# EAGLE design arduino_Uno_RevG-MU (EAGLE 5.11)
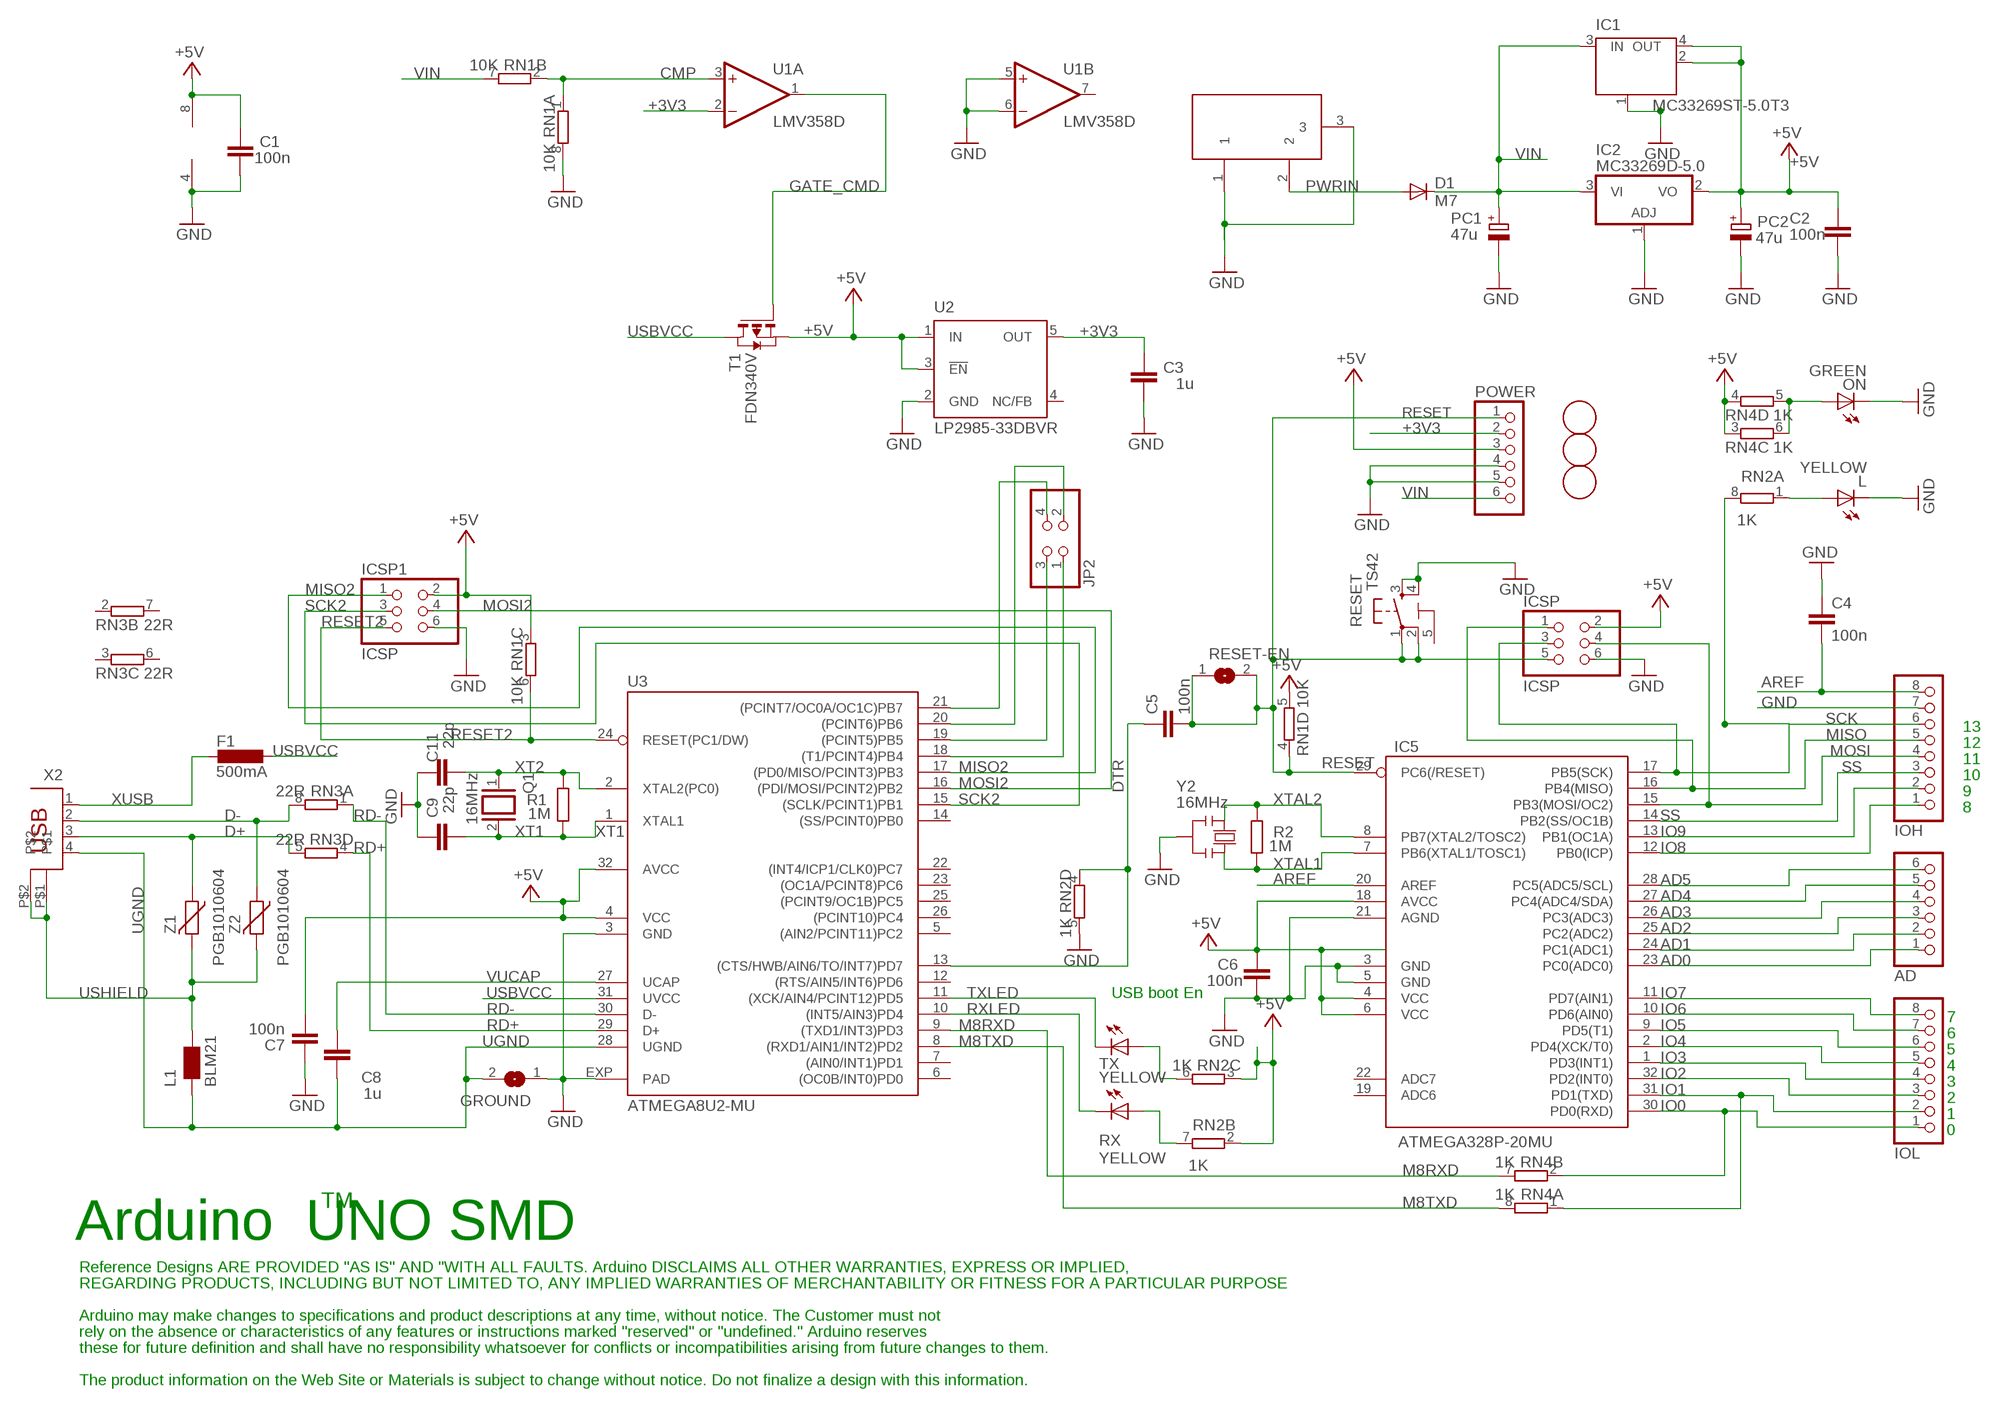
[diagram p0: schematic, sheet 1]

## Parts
AD  PINHD-1X6  [1X06]
C1  100n  C-EU0603-RND  [C0603-ROUND]
C2  100n  C-EU0603-RND  [C0603-ROUND]
C3  1u  C-EU0603-RND  [C0603-ROUND]
C4  100n  C-EU0603-RND  [C0603-ROUND]
C5  100n  C-EU0603-RND  [C0603-ROUND]
C6  100n  C-EU0603-RND  [C0603-ROUND]
C7  100n  C-EU0603-RND  [C0603-ROUND]
C8  1u  C-EU0603-RND  [C0603-ROUND]
C9  22p  C-EU0603-RND  [C0603-ROUND]
C11  22p  C-EU0603-RND  [C0603-ROUND]
D1  M7  DIODE-SMB  [SMB]
F1  500mA  L-EUL1812  [L1812]
GROUND  SJ  [SJ]
IC1  MC33269ST-5.0T3  MC33269ST-3.3T3  [SOT223]
IC2  MC33269D-5.0  [DPACK]
IC5  ATMEGA328P-20MU  MEGA8-MI  [MLF32]
ICSP  ICSP  PINHD-2X3  [2X03]
ICSP1  ICSP  PINHD-2X3  [2X03]
IOH  PINHD-1X8  [1X08]
IOL  PINHD-1X8  [1X08]
JP2  PINHD-2X2  [2X02]
L  YELLOW  LEDCHIP-LED0805  [CHIP-LED0805]
L1  BLM21  WE-CBF_0805  [0805]
ON  GREEN  LEDCHIP-LED0805  [CHIP-LED0805]
PC1  47u  CPOL-EUD  [PANASONIC_D]
PC2  47u  CPOL-EUD  [PANASONIC_D]
POWER  PINHD-1X6  [1X06]
Q1  16MHz  XTAL/S  [QS]
R1  1M  R-EU_R0603  [R0603-ROUND]
R2  1M  R-EU_R0603  [R0603-ROUND]
RESET  TS42  [TS42]
RESET-EN  SJ  [SJ]
RN1  10K  4R-NCAY16  [CAY16]
RN2  1K  4R-NCAY16  [CAY16]
RN3  22R  4R-NCAY16  [CAY16]
RN4  1K  4R-NCAY16  [CAY16]
RX  YELLOW  LEDCHIP-LED0805  [CHIP-LED0805]
T1  FDN340V  PMOSSOT23  [SOT-23]
TX  YELLOW  LEDCHIP-LED0805  [CHIP-LED0805]
U1  LMV358D  LM358D  [SO08]
U2  LP2985-33DBVR  TPS77033  [SOT23-DBV]
U3  ATMEGA8U2-MU  [QFN32]
U$3  FIDUCIALMOUNT  [FIDUCIA-MOUNT]
U$4  FIDUCIALMOUNT  [FIDUCIA-MOUNT]
U$6  FIDUCIALMOUNT  [FIDUCIA-MOUNT]
X1  DC21MMX  [DC-21MM]
X2  PN61729  [PN61729]
Y2  16MHz  RESONATORMU  [RESONATOR]
Z1  PGB1010604  VARISTORCN0603  [CT/CN0603]
Z2  PGB1010604  VARISTORCN0603  [CT/CN0603]

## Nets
+3V3: C3.2 POWER.2 U1.2(A:-IN) U2.5(OUT)
+5V [usbvcc]: C1.2 C2.2 C6.2 C7.1 IC1.2(OUT) IC1.4(OUT) IC2.2(VO) IC5.4(VCC) IC5.6(VCC) IC5.18(AVCC) ICSP1.2 ICSP.2 PC2.+ POWER.3 RN1.3 RN1.5 RN2.2 RN2.3 RN4.3 RN4.4 T1.2(S) U1.8(P:V+) U2.1(IN) U2.3(!EN) U3.4(VCC) U3.32(AVCC)
AD0: AD.1 IC5.23(PC0(ADC0))
AD1: AD.2 IC5.24(PC1(ADC1))
AD2: AD.3 IC5.25(PC2(ADC2))
AD3: AD.4 IC5.26(PC3(ADC3))
AD4: AD.5 IC5.27(PC4(ADC4/SDA))
AD5: AD.6 IC5.28(PC5(ADC5/SCL))
AREF [aref]: C4.2 IC5.20(AREF) IOH.8
CMP: RN1.1 RN1.2 U1.3(A:+IN)
D+: RN3.5 X2.3 Z1.1
D-: RN3.8 X2.2 Z2.1
DTR: C5.1 RN2.4 U3.13((CTS/HWB/AIN6/TO/INT7)PD7)
GATE_CMD: T1.3(G) U1.1(A:OUT)
GND [gnd]: C1.1 C2.1 C3.1 C4.1 C6.1 C7.2 C9.2 C11.2 GROUND.1 IC1.1(GND/ADJ) IC2.1(ADJ) IC5.3(GND) IC5.5(GND) IC5.21(AGND) ICSP1.6 ICSP.6 IOH.7 L.C ON.C PC1.- PC2.- POWER.4 POWER.5 RESET.3 RESET.4 RN1.8 RN2.5 U1.4(P:V-) U1.5(B:+IN) U1.6(B:-IN) U2.2(GND) U3.3(GND) U3.EXP(PAD) X1.1 X1.3 Y2.2
IO0: IC5.30(PD0(RXD)) IOL.1 RN4.2
IO1: IC5.31(PD1(TXD)) IOL.2 RN4.1
IO2: IC5.32(PD2(INT0)) IOL.3
IO3: IC5.1(PD3(INT1)) IOL.4
IO4: IC5.2(PD4(XCK/T0)) IOL.5
IO5: IC5.9(PD5(T1)) IOL.6
IO6: IC5.10(PD6(AIN0)) IOL.7
IO7: IC5.11(PD7(AIN1)) IOL.8
IO8: IC5.12(PB0(ICP)) IOH.1
IO9: IC5.13(PB1(OC1A)) IOH.2
M8RXD: RN4.7 U3.9((TXD1/INT3)PD3)
M8TXD: RN4.8 U3.8((RXD1/AIN1/INT2)PD2)
MISO: IC5.16(PB4(MISO)) ICSP.1 IOH.5
MISO2: ICSP1.1 U3.17((PD0/MISO/PCINT3)PB3)
MOSI: IC5.15(PB3(MOSI/OC2)) ICSP.4 IOH.4
MOSI2: ICSP1.4 U3.16((PDI/MOSI/PCINT2)PB2)
N$1: L.A RN2.1
N$2: JP2.1 U3.18((T1/PCINT4)PB4)
N$3: ON.A RN4.5 RN4.6
N$4: JP2.3 U3.19((PCINT5)PB5)
N$5: JP2.2 U3.20((PCINT6)PB6)
N$6: JP2.4 U3.21((PCINT7/OC0A/OC1C)PB7)
N$35: RN2.7 RX.A
N$36: RN2.6 TX.A
PWRIN [power]: D1.A X1.2
RD+: RN3.4 U3.29(D+)
RD-: RN3.1 U3.30(D-)
RESET: C5.2 IC5.29(PC6(/RESET)) ICSP.5 POWER.1 RESET-EN.1 RESET-EN.2 RESET.1 RESET.2 RN1.4
RESET2: ICSP1.5 RN1.6 U3.24(RESET(PC1/DW))
RXLED: RX.C U3.10((INT5/AIN3)PD4)
SCK: IC5.17(PB5(SCK)) ICSP.3 IOH.6 RN2.8
SCK2: ICSP1.3 U3.15((SCLK/PCINT1)PB1)
SS: IC5.14(PB2(SS/OC1B)) IOH.3
TXLED: TX.C U3.11((XCK/AIN4/PCINT12)PD5)
UGND [gnd]: C8.2 GROUND.2 L1.1 U3.28(UGND) X2.4
USBVCC [usbvcc]: F1.1 T1.1(D) U3.31(UVCC)
USHIELD [gnd]: L1.2 X2.P$1 X2.P$2 Z1.2 Z2.2
VIN [power]: D1.C IC1.3(IN) IC2.3(VI) PC1.+ POWER.6 RN1.7
VUCAP: C8.1 U3.27(UCAP)
XT1: C9.1 Q1.2 R1.1 U3.1(XTAL1)
XT2: C11.1 Q1.1 R1.2 U3.2(XTAL2(PC0))
XTAL1: IC5.7(PB6(XTAL1/TOSC1)) R2.1 Y2.3
XTAL2: IC5.8(PB7(XTAL2/TOSC2)) R2.2 Y2.1
XUSB [usbvcc]: F1.2 X2.1
Unconnected: IC5.19(ADC6) IC5.22(ADC7) RN3.2 RN3.3 RN3.6 RN3.7 U1.7(B:OUT) U2.4(NC/FB) U3.5((AIN2/PCINT11)PC2) U3.6((OC0B/INT0)PD0) U3.7((AIN0/INT1)PD1) U3.12((RTS/AIN5/INT6)PD6) U3.14((SS/PCINT0)PB0) U3.22((INT4/ICP1/CLK0)PC7) U3.23((OC1A/PCINT8)PC6) U3.25((PCINT9/OC1B)PC5) U3.26((PCINT10)PC4)

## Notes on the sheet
- 13
- 12
- 11
- 10
- 9
- 8
- USB boot En
- 7
- 6
- 5
- 4
- 3
- 2
- 1
- 0
- TM
- Arduino  UNO SMD
- Reference Designs ARE PROVIDED "AS IS" AND "WITH ALL FAULTS. Arduino DISCLAIMS ALL OTHER WARRANTIES, EXPRESS OR IMPLIED,
- REGARDING PRODUCTS, INCLUDING BUT NOT LIMITED TO, ANY IMPLIED WARRANTIES OF MERCHANTABILITY OR FITNESS FOR A PARTICULAR PURPOSE
- Arduino may make changes to specifications and product descriptions at any time, without notice. The Customer must not
- rely on the absence or characteristics of any features or instructions marked "reserved" or "undefined." Arduino reserves
- these for future definition and shall have no responsibility whatsoever for conflicts or incompatibilities arising from future changes to them.
- The product information on the Web Site or Materials is subject to change without notice. Do not finalize a design with this information.

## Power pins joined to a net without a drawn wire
5-GND: RESET.5(5-GND)

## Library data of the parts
AD POWER = pinhead:PINHD-1X6: PIN HEADER
C1-C9 C11 = SmartPrj:C-EU: CAPACITOR, European symbol
D1 = diode:DIODE-: DIODE
F1 = rcl:L-EU: INDUCTOR, European symbol
GROUND RESET-EN = jumper:SJ: SMD solder JUMPER
IC1 = linear:MC33269ST*: Adjustable Output Low Dropout Voltage Regulator 800 mA Source: http://www.onsemi.com/pub/Collateral/MC33269-D.PDF
IC2 = linear:MC33269?*: Adjustable Output Low Dropout Voltage Regulator 800 mA Source: http://www.onsemi.com/pub/Collateral/MC33269-D.PDF
IC5 = idii:MEGA8: MICROCONTROLLER 8 Kbytes FLASH 1 kbytes SRAM 512 bytes EEPROM USART 6-channel 10 bit ADC 2-channel 8 bit ADC Source: avr.lbr
ICSP ICSP1 = pinhead:PINHD-2X3: PIN HEADER
IOH IOL = pinhead:PINHD-1X8: PIN HEADER
JP2 = pinhead:PINHD-2X2: PIN HEADER
L ON RX TX = led:LED: LED
L1 = wuerth-elektronik:WE-CBF: SMD EMI Suppression Ferrite Beads
PC1 PC2 = rcl:CPOL-EU: POLARIZED CAPACITOR, European symbol
Q1 = special:XTAL/S: CRYSTAL
R1 R2 = SmartPrj:R-EU_: RESISTOR, European symbol
RESET = st-mod v1.4:TS42: TS42 Dongnan Electronics Tact switch VDC 12V - 50mA
RN1-RN4 = resistor-dil:4R-N: Array Chip Resistor Source: RS Component / Phycomp
T1 = zetex:PMOSSOT23: MOS FET
U1 = linear:LM358: OP AMP also LM158; LM258; LM2904 Source: http://cache.national.com/ds/LM/LM158.pdf
U2 = texas:TPS770*: ULTRALOW-POWER 50-mA LOW-DROPOUT LINEAR REGULATORS 50-mA Low-Dropout Regulator Source: http://focus.ti.com/lit/ds/symlink/tps77001.pdf
U3 = atmel:ATMEGA8U2-MU
U$3 U$4 U$6 = SmartPrj:FIDUCIALMOUNT
X1 = powersupply:DC21MM
X2 = SmartPrj:PN61729: BERG USB connector
Y2 = SmartPrj:RESONATOR
Z1 Z2 = varistor:VARISTOR: VARISTOR

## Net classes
0 default: width 0.152 mm, clearance 0.152 mm
1 power: width 0.406 mm, drill 0.61 mm, clearance 0.152 mm
2 gnd: width 0.203 mm, drill 0.559 mm, clearance 0.152 mm
3 usbvcc: width 0.203 mm, drill 0.61 mm, clearance 0.152 mm
4 aref: width 0.203 mm, drill 0.61 mm, clearance 0.152 mm

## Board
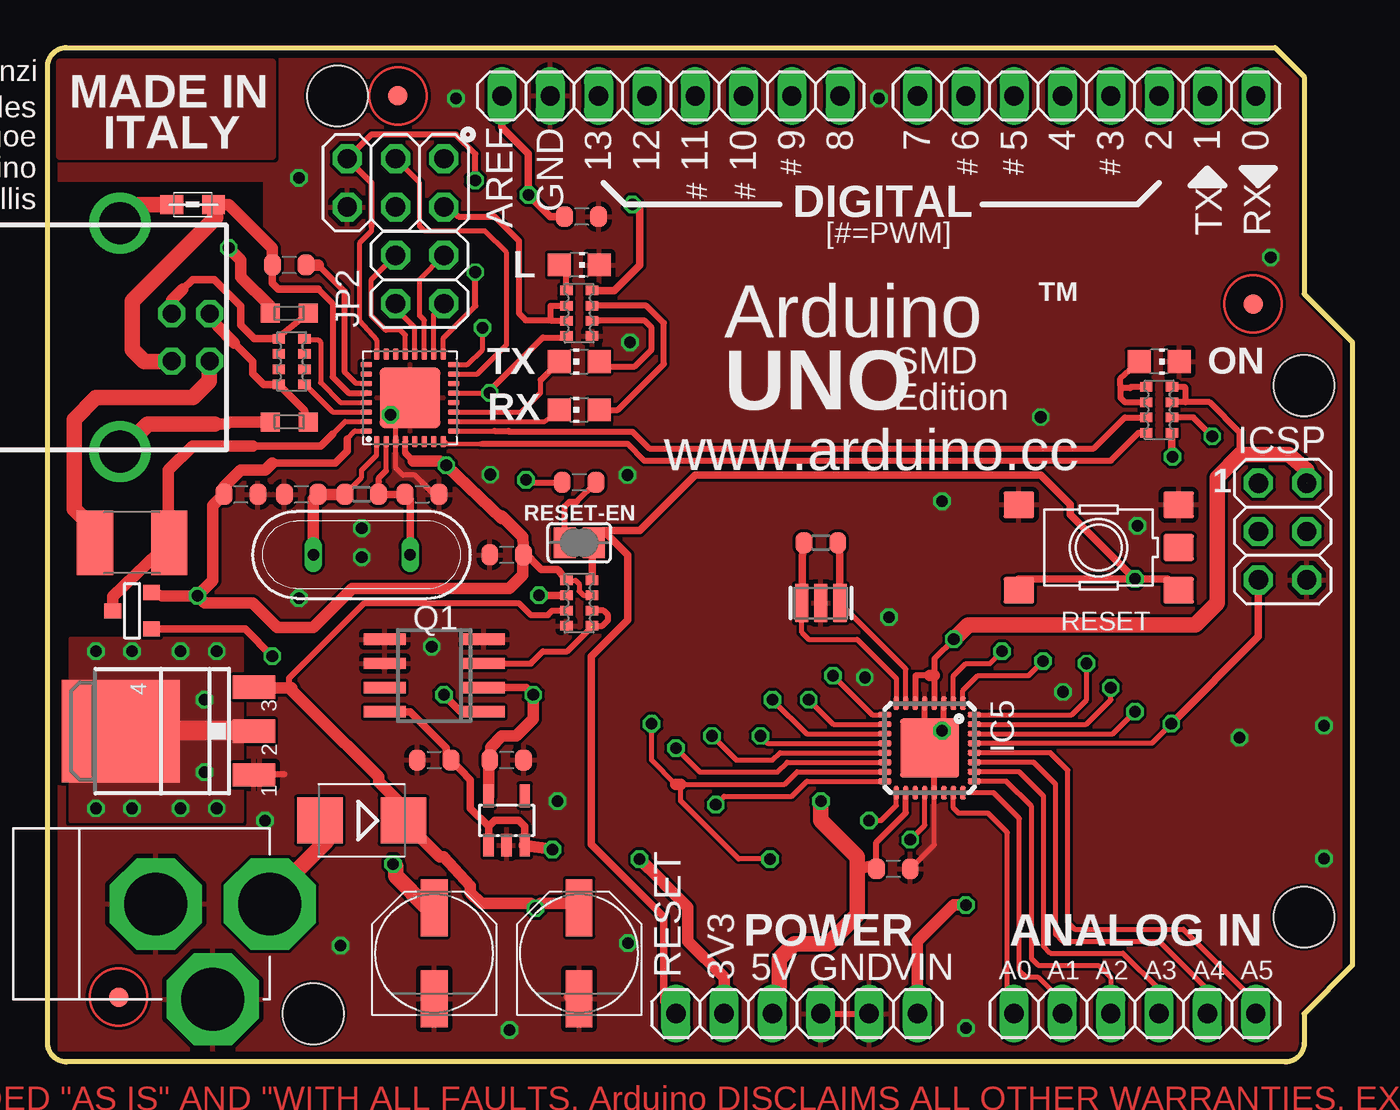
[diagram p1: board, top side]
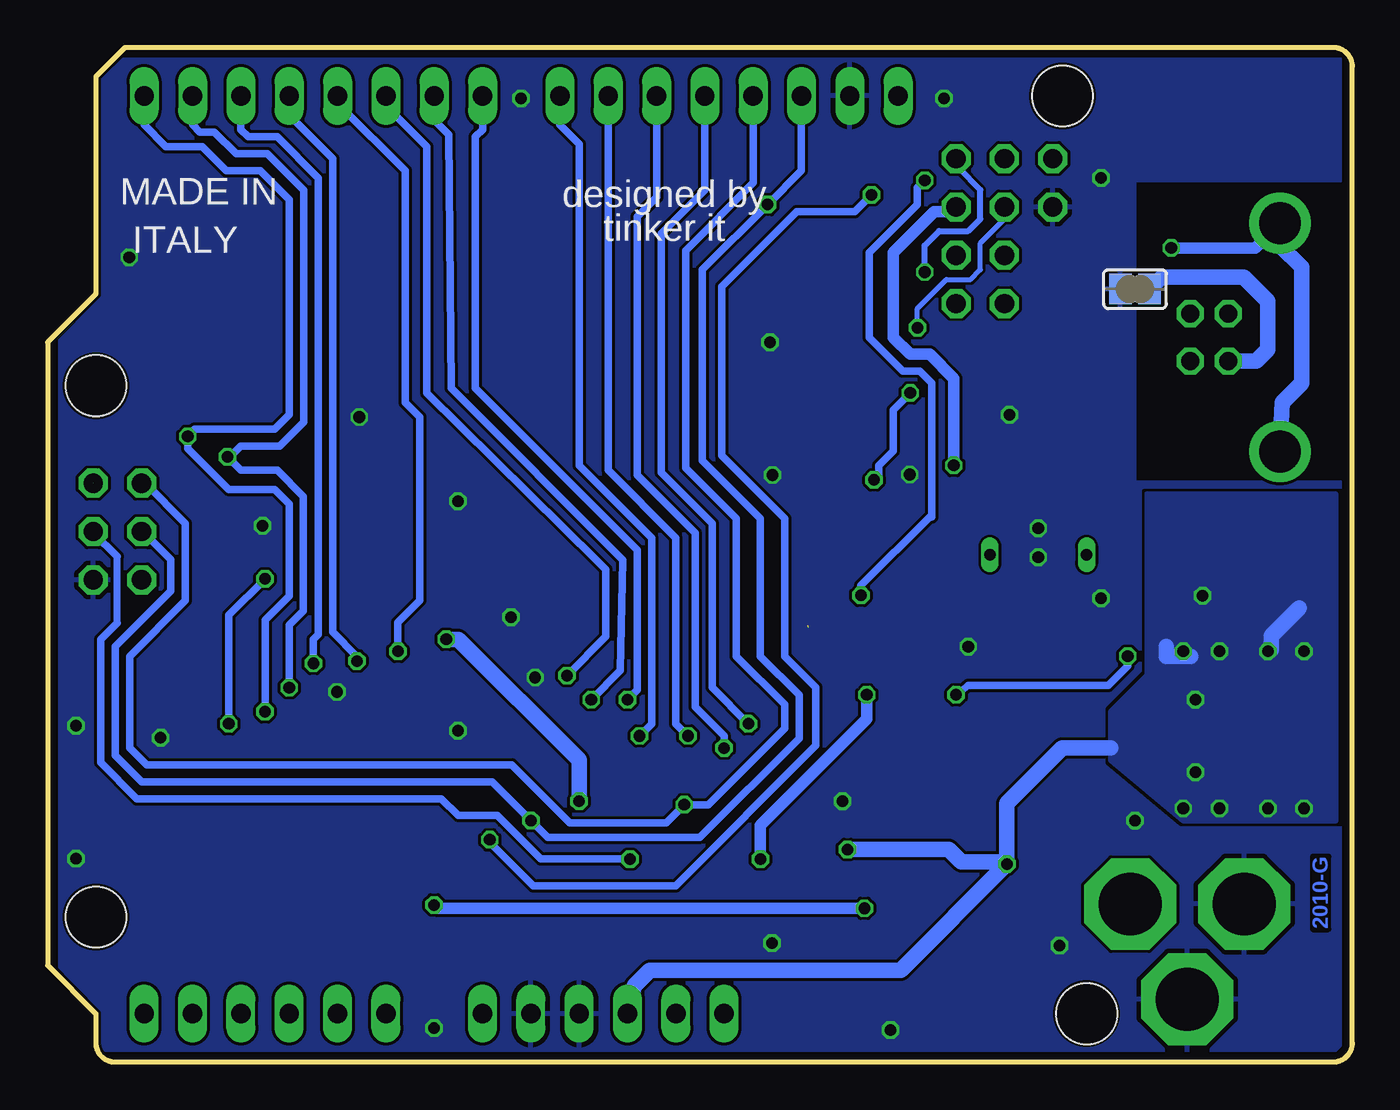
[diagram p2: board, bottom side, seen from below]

Size 68.58 x 53.34 mm. Coordinates in mm from the lower left corner, seen from the top.
Outline: 64.52,53.34 66.04,51.82 66.04,40.39 68.58,37.85 68.58,5.08 66.04,2.54 66.04,1 arc-90 65.04,0 1,0 arc-90 0,1 0,52.34 arc-90 1,53.34 64.52,53.34
Copper layers (1*16): Top 0.035mm / dielectric 1.5mm / Bottom 0.035mm
Design rules "default *": minimum track width 6mil, minimum drill 10mil, track to track 6mil, track to pad 6mil, pad to pad 6mil, via to via 6mil, smd to smd 6mil, copper to edge 6mil, drill to drill 6mil, minimum pad ring 6mil, minimum via ring 6mil, stop-mask expansion 1mil, vias tented up to drill 0mil, thermal gap 10mil
Holes 3.2 mm at 66.04,35.56 66.04,7.62 15.24,50.8 13.97,2.54
vRestrict: area 22.9,44.1 to 24.6,49.1; area 25.4,45.5 to 27.1,49.1; area 28.4,45.3 to 29.6,48.8; area 31,45.3 to 32.1,48.8; area 33.5,45.3 to 34.7,48.8; area 36.1,45.3 to 37.2,48.8; area 38.7,47.2 to 39.9,48.8; area 40.3,45.1 to 47.6,46.9; area 60.3,44.2 to 61.7,46.7; area 62.9,44.2 to 64.3,46.7; area 61.3,35.8 to 64.8,37.2; area 0.6,21.8 to 2,30.1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

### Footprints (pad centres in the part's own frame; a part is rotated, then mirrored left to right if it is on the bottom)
1X06 = drill 1.016 long: 1 -6.35,0; 2 -3.81,0; 3 -1.27,0; 4 1.27,0; 5 3.81,0; 6 6.35,0
C0603-ROUND = smd 0.898 x 1.1: 1 -0.889,0; 2 0.889,0
SMB = smd 2.4 x 2.4: A 2.2,0; C -2.2,0
L1812 = smd 1.9 x 3.4: 1 -1.95,0; 2 1.95,0
SJ = smd 1.168 x 1.6: 1 -0.762,0; 2 0.762,0
SOT223 = smd 1.219 x 2.235: 1 -2.311,-3.099; 2 0,-3.099; 3 2.311,-3.099 | smd 3.6 x 2.2: 4 0,3.099
DPACK = smd 1 x 1.6: 1 -2.28,-4.8; 3 2.28,-4.8 | smd 5.4 x 6.2: 2 0,2.5
MLF32 = smd 0.7 x 0.3: 1 -2.35,1.75; 2 -2.35,1.25; 3 -2.35,0.75; 4 -2.35,0.25; 5 -2.35,-0.25; 6 -2.35,-0.75; 7 -2.35,-1.25; 8 -2.35,-1.75; 17 2.35,-1.75; 18 2.35,-1.25; 19 2.35,-0.75; 20 2.35,-0.25; 21 2.35,0.25; 22 2.35,0.75; 23 2.35,1.25; 24 2.35,1.75 | smd 0.3 x 0.7: 9 -1.75,-2.35; 10 -1.25,-2.35; 11 -0.75,-2.35; 12 -0.25,-2.35; 13 0.25,-2.35; 14 0.75,-2.35; 15 1.25,-2.35; 16 1.75,-2.35; 25 1.75,2.35; 26 1.25,2.35; 27 0.75,2.35; 28 0.25,2.35; 29 -0.25,2.35; 30 -0.75,2.35; 31 -1.25,2.35; 32 -1.75,2.35 | smd 3.1 x 3.1: PAD 0,0
2X03 = drill 1.016 octagon: 1 -2.54,-1.27; 2 -2.54,1.27; 3 0,-1.27; 4 0,1.27; 5 2.54,-1.27; 6 2.54,1.27
1X08 = drill 1.016 long: 1 -8.89,0; 2 -6.35,0; 3 -3.81,0; 4 -1.27,0; 5 1.27,0; 6 3.81,0; 7 6.35,0; 8 8.89,0
2X02 = drill 1.016 octagon: 1 -1.27,-1.27; 2 -1.27,1.27; 3 1.27,-1.27; 4 1.27,1.27
CHIP-LED0805 = smd 1.2 x 1.2: A 0,-1.05; C 0,1.05
0805 = smd 1.2 x 1: 1 -1.1,0; 2 1.1,0
PANASONIC_D = smd 3 x 1.4: + 2.4,0; - -2.4,0
QS = drill 0.61 long: 1 -2.54,0; 2 2.54,0
R0603-ROUND = smd 0.898 x 1.1: 1 -0.889,0; 2 0.889,0
TS42 = smd 1.6 x 1.4: 1 -4.2,2.25; 2 4.2,2.25; 3 -4.2,-2.25; 4 4.2,-2.25; 5 -4.2,0
CAY16 = smd 0.5 x 0.65: 1 -1.2,-0.675; 2 -0.4,-0.675; 3 0.4,-0.675; 4 1.2,-0.675; 5 1.2,0.675; 6 0.4,0.675; 7 -0.4,0.675; 8 -1.2,0.675
SOT-23 = smd 0.787 x 0.889: 1 0.025,-1.016; 2 -0.94,1.016; 3 0.991,1.016
SO08 = smd 0.6 x 2.2: 1 -1.905,-2.6; 2 -0.635,-2.6; 3 0.635,-2.6; 4 1.905,-2.6; 5 1.905,2.6; 6 0.635,2.6; 7 -0.635,2.6; 8 -1.905,2.6
SOT23-DBV = smd 0.55 x 1.2: 1 -0.95,-1.3; 2 0,-1.3; 3 0.95,-1.3; 4 0.95,1.3; 5 -0.95,1.3
QFN32 = smd 0.6 x 0.3: 1 -2.3,1.75; 2 -2.3,1.25; 3 -2.3,0.75; 4 -2.3,0.25; 5 -2.3,-0.25; 6 -2.3,-0.75; 7 -2.3,-1.25; 8 -2.3,-1.75; 17 2.3,-1.75; 18 2.3,-1.25; 19 2.3,-0.75; 20 2.3,-0.25; 21 2.3,0.25; 22 2.3,0.75; 23 2.3,1.25; 24 2.3,1.75 | smd 0.3 x 0.6: 9 -1.75,-2.3; 10 -1.25,-2.3; 11 -0.75,-2.3; 12 -0.25,-2.3; 13 0.25,-2.3; 14 0.75,-2.3; 15 1.25,-2.3; 16 1.75,-2.3; 25 1.75,2.3; 26 1.25,2.3; 27 0.75,2.3; 28 0.25,2.3; 29 -0.25,2.3; 30 -0.75,2.3; 31 -1.25,2.3; 32 -1.75,2.3 | smd 3.2 x 3.2: EXP 0,0
FIDUCIA-MOUNT = smd 1.016 x 1.016: P$1 0,0
DC-21MM = drill 3.302 pad 4.826 octagon: 1 -5.08,-3.353; 2 -0.076,-6.35; 3 -0.076,-0.356
PN61729 = drill 0.95 octagon: 1 1.25,4.71; 2 -1.25,4.71; 3 -1.25,2.71; 4 1.25,2.71 | drill 2.2 round: P$1 -6,0; P$2 6,0
RESONATOR = smd 0.7 x 2: 1 -1,0; 2 0,0; 3 1,0
CT/CN0603 = smd 1 x 1: 1 -1,0; 2 1,0

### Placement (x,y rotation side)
AD  57.15,2.54 0 top
C1  20.32,15.88 0 top
C2  10.16,29.84 180 top
C3  24.13,15.88 180 top
C4  28.07,44.45 180 top
C5  27.94,30.48 0 top
C6  44.45,10.16 180 top
C7  24.13,26.67 180 top
C8  12.7,41.91 180 top
C9  13.34,29.84 180 top
C11  19.68,29.84 0 top
D1  16.51,12.7 180 top
F1  4.45,27.3 180 top
GROUND  11.43,40.64 0 bottom
IC1  7.75,17.4 90 top
IC2  6.35,17.4 90 top
IC5  46.35,16.51 270 top
ICSP  64.91,27.89 270 top
ICSP1  18.29,46.23 180 top
IOH  32.77,50.8 180 top
IOL  54.61,50.8 180 top
JP2  19.56,41.15 90 top
L  27.94,41.91 270 top
L1  7.62,45.09 180 top
ON  58.42,36.83 270 top
PC1  27.94,5.71 90 top
PC2  20.32,5.71 90 top
POWER  39.37,2.54 0 top
Q1  16.51,26.67 180 top
R1  16.51,29.84 0 top
R2  40.64,27.3 180 top
RESET  55.24,27.05 180 top
RESET-EN  27.94,27.3 0 top
RN1  27.94,24.13 90 top
RN2  27.94,39.37 270 top
RN3  12.83,36.83 90 top
RN4  58.42,34.29 90 top
RX  27.94,34.29 90 top
T1  4.45,23.75 270 top
TX  27.94,36.83 90 top
U1  20.32,20.32 90 top
U2  24.13,12.7 0 top
U3  19.05,34.92 90 top
U$3  18.41,50.8 0 top
U$4  63.37,39.85 0 top
U$6  3.73,3.41 0 top
X1  5.33,8.38 90 top
X2  3.81,38.1 270 top
Y2  40.64,24.13 0 top
Z1  12.7,39.37 180 top
Z2  12.7,33.66 180 top

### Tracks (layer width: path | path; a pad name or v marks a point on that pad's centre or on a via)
+3V3  (via drill 0.61)
  Top 0.406: U1.2 25.15,19.68 v25.53,19.3
  Top 0.61: POWER.2 35.56,4.45 33.66,6.35 33.66,8.13 v31.11,10.67 31.62,10.16 | U2.5 23.18,15.78 C3.2 23.28,16.55 23.88,17.14 24.64,17.14 25.53,18.03 v25.53,19.3
  Bottom 0.61: v31.11,10.67 30.99,10.54 31.11,10.54 31.11,12.45 25.53,18.03 v25.53,19.3
+5V  (via drill 0.61)  (1 unrouted)
  Top 0.254: U3.32 16.16,33.17 15.75,32.77 | RN1.3 28.18,24.53 27.94,24.77 27.94,25.15 27.76,25.33 RN1.5
  Top 0.305: 18.8,32.02 U3.4 | 59.82,34.69 61.07,34.69 62.66,33.1 62.66,31.93 | 59.82,34.69 RN4.3 | RN4.4 59.76,35.49 59.82,35.43 59.82,34.69 | RN2.2 26.43,39.77 26.43,39.01 | ICSP1.2 21.08,44.96 21.59,44.45 23.5,44.45 24.77,43.18 24.77,39.37 25.13,39.01 26.43,39.01 | RN2.3 26.47,38.97 26.43,39.01 | IC5.4 46.6,20.32 46.6,21.2 v47.62,22.23 | IC5.6 45.6,20.32 46.35,20.32 | C6.2 43.56,11.56 45.1,13.1 IC5.18
  Top 0.356: 19.23,31.6 18.8,32.02
  Top 0.406: 23.18,12.38 U2.1 | 23.18,12.38 23.5,12.7 24.77,12.7 25.08,12.38 U2.3 | U1.8 19.05,18.41 20.95,16.51 20.95,16.09 C1.2 22.23,14.82 22.23,13.34 23.18,12.38 | RN1.5 26.87,25.84 26.8,25.91 25.96,25.91 24.98,26.89 | 11.81,31.5 15.11,31.5 15.75,32.13 15.75,32.77
  Top 0.508: 11.02,17.42 IC1.2
  Top 0.61: U2.3 25.05,11.4 v26.54,11.18 | C6.2 43.6,10.38 42.55,10.16 | T1.2 6.02,24.51 v7.87,24.51 | v7.87,24.51 8.68,25.31 8.68,29.25 C2.2 9.27,30.23 10.16,31.11 11.43,31.11 11.81,31.5 | v7.87,24.51 8.26,24.13 10.79,24.13 12.06,22.86 13.97,22.86 16,24.89 24.26,24.89 24.98,25.61 24.98,26.89 C7.1 24.98,27.6 23.88,28.7 23.88,28.57 v20.95,31.37 20.6,31.6 19.23,31.6 | 46.6,20.32 46.35,20.32
  Top 0.813: POWER.3 38.46,4.01 38.46,5.44 39.24,6.22 41.02,6.22 42.55,7.75 42.55,10.16 42.55,10.79 40.64,12.7 v40.64,13.72 | 66.17,30.44 66.17,31.11 65.23,31.93 62.66,31.93 61.47,30.73 61.47,24.13 60.33,22.99 48.39,22.99 v47.62,22.23 | PC2.+ 19.95,8.12 18.29,9.78 18.29,10.29 v18.16,10.41
  Top 1.016: IC1.4 5.84,17.4 5.87,17.42 11.02,17.42
  Bottom 0.61: 20.56,10.53 20.57,10.54 | v4.45,21.59 4.27,21.67 | v20.95,31.37 20.95,35.94 22.23,37.21 23.24,37.21 24.13,38.1 24.13,42.55 21.97,44.7 21.08,44.7 ICSP1.2
  Bottom 0.813: POWER.3 37.74,4.01 36.93,4.83 23.75,4.83 v18.16,10.41 | v8.89,21.59 8.51,21.34 9.78,21.34 9.78,21.84 | 4.27,21.67 4.27,22.4 2.79,23.88 | 12.7,16.51 15.24,16.51 18.16,13.59 v18.16,10.41 | 20.57,10.54 21.21,11.18 v26.54,11.18 | 20.56,10.53 18.27,10.53 v18.16,10.41 | v40.64,13.72 40.64,15.88 46.99,22.23 v47.62,22.23
  other vias: 2.54,21.59 6.99,21.59 2.54,13.34 4.45,13.34 6.99,13.34 8.89,13.34 8.26,15.24 8.26,19.05
  pour Top (no thermals): 1.91,21.59 2.54,22.23 8.26,22.23 10.16,20.32 10.16,14.61 8.26,12.7 2.54,12.7 1.91,13.34
  pour Bottom (no thermals): 0.89,29.84 9.53,29.84 10.79,29.84 10.79,20.32 12.7,18.41 12.7,15.88 8.89,12.7 0.89,12.7
  pour Top (no thermals): 1.91,21.59 2.54,22.23 8.26,22.23 10.16,20.32 10.16,14.61 8.26,12.7 2.54,12.7 1.91,13.34
  pour Top (no thermals): 1.27,12.7 1.27,22.23 10.16,22.23 10.16,12.7
AD0
  Top 0.254: AD.1 50.44,3 50.44,12.06 49.43,13.08 47.88,13.08 47.6,13.36 IC5.23
AD1
  Top 0.254: IC5.24 49.72,14.16 51.08,12.8 51.08,4.8 51.44,4.45 52.07,4.45 53.34,3.17 AD.2
AD2
  Top 0.254: IC5.25 50.39,14.76 51.71,13.44 51.71,5.44 52.07,5.08 55.24,5.08 55.88,4.45 AD.3
AD3
  Top 0.254: IC5.26 51.06,15.26 52.35,13.97 52.35,6.07 52.7,5.71 56.52,5.71 58.42,3.81 AD.4
AD4
  Top 0.254: IC5.27 51.83,15.76 52.98,14.61 52.98,6.71 53.34,6.35 58.42,6.35 60.96,3.81 AD.5
AD5
  Top 0.254: IC5.28 52.7,16.26 53.62,15.34 53.62,7.34 53.98,6.99 59.69,6.99 63.5,3.17 AD.6
AREF  (via drill 0.61)
  Top 0.254: IC5.20 46.1,12.45 v45.34,11.68
  Top 0.406: IOH.8 23.88,49.15 25.27,47.75 v25.27,45.59 26.42,44.45 C4.2
  Bottom 0.406: v25.27,45.59 26.16,44.7 29.21,44.7 33.15,40.77 33.15,31.88 29.84,28.57 29.84,21.34 28.19,19.68 28.19,16.64 35.56,9.27 43.05,9.27 45.47,11.68 v45.34,11.68
CMP  (1 unrouted)
  Top 0.305: U1.3 25.4,20.95 26.04,21.59 27.3,21.59 28.57,22.86 | RN1.2 29.23,23.73 29.46,23.5 29.46,23.24 29.15,22.93 RN1.1
D+
  Top 0.305: Z1.1 12.1,38.1 RN3.5
  Top 0.406: 7.11,40.64 7.62,41.15 8.76,41.15 10.16,39.75 10.16,38.73 10.87,38.03 RN3.5
  Top 0.61: X2.3 6.52,40.05 7.11,40.64
D-
  Top 0.406: 9.82,37.81 10.79,36.83 10.79,36.2 11.36,35.63 RN3.8 13.49,34.29 Z2.1
  Top 0.61: X2.2 8.91,38.72 9.82,37.81
DTR  (via drill 0.61)
  Top 0.254: U3.13 23.12,35.17 v23.24,35.18
  Top 0.305: C5.1 25.27,30.48 v25.15,30.61 | RN2.4 27.2,38.1 26.04,38.1 23.24,35.31 v23.24,35.18
  Bottom 0.406: v23.24,35.18 24.13,34.29 24.13,32.13 24.89,31.37 24.89,30.86 v25.15,30.61 25.27,30.48
GATE_CMD  (via drill 0.61)
  Top 0.406: U1.1 21.72,18.41 v20.83,19.3 | v11.81,21.34 10.39,22.76 T1.3
  Bottom 0.406: v11.81,21.34 11.81,20.83 12.83,19.81 20.19,19.81 v20.83,19.3
GND  (via drill 0.61)
  Top 0.254: 18.3,33.9 18.55,33.64 | 18.3,33.9 U3.3 18.3,31.23 18.67,30.86 19.3,30.86 19.68,30.48 | IC5.21 46.6,11.43 C6.1 | 46.6,16.26 46.1,16.76 | v47.02,17.42 47.1,17.51 | U3.EXP 18.92,34.92 v18.03,34.04 18.16,34.04 18.3,33.9
  Top 0.305: POWER.4 POWER.5 | IC2.1 12.45,15.14 IC1.1 | 19.86,3.3 PC2.- | C11.2 20.32,29.84 19.68,30.48 | 46.1,16.76 IC5.5 | IC5.21 46.6,16.26 | 47.1,17.51 IC5.3
  Top 0.406: 27.3,3.43 PC1.-
  Bottom 0.305: GROUND.1 10.79,40.64
  other vias: 30.51,6.25 26.8,13.72 15.39,6.12 23.27,30.89 52.2,33.91 30.61,37.85 11.43,12.7 53.37,19.46 30.48,30.86 43.69,50.67 48.26,1.78 16.51,28.07 57.28,28.19 24.28,1.68 67.08,10.69 64.29,42.32 13.21,24.38 67.08,17.68 20.19,21.84 13.21,46.48 21.46,50.67 47.02,29.49 16.51,26.54 62.64,17.04 44.22,23.39 42.95,20.22
  pour Bottom (rank 2): 0.64,52.7 67.69,52.7 67.94,52.45 67.94,0.64 0.89,0.64 0.64,0.89 0.64,30.48 11.43,30.48 11.43,46.35 0.64,46.35
  pour Top (rank 2): 0.64,52.7 67.94,52.7 67.94,0.64 0.64,0.64 0.64,30.48 11.43,30.48 11.43,46.35 0.64,46.35
IO0  (via drill 0.61)
  Top 0.254: IC5.30 55.99,17.26 v57.15,18.41
  Top 0.305: RN4.2 60.22,33.89 v61.21,32.89
  Bottom 0.406: IOL.1 63.5,49.28 62.36,48.13 60.45,48.13 59.18,46.86 57.4,46.86 55.88,45.34 55.88,34.04 56.64,33.27 60.83,33.27 v61.21,32.89 61.21,32.26 59.05,30.1 56.64,30.1 55.88,29.34 55.88,24.51 57.15,23.24 v57.15,18.41
IO1  (via drill 0.61)
  Top 0.254: IC5.31 54.59,17.76 55.88,19.05 v55.88,19.68
  Top 0.406: RN4.1 59.09,31.86 v59.13,31.83
  Bottom 0.406: 60.96,50.55 IOL.2 60.96,49.28 60.58,48.9 59.82,48.9 58.67,47.75 57.02,47.75 55.12,45.85 55.12,33.66 56.39,32.38 58.42,32.38 58.85,31.95 59,31.95 v59.13,31.83 58.42,31.11 56.52,31.11 55.14,29.74 55.14,23.72 55.88,22.99 v55.88,19.68
IO2  (via drill 0.61)
  Top 0.254: IC5.32 53.82,18.26 54.61,19.05 v54.61,20.95
  Bottom 0.406: 58.42,50.42 IOL.3 58.42,49.02 58.04,48.64 56.52,48.64 54.36,46.48 54.36,22.48 54.61,22.23 v54.61,20.95
IO3  (via drill 0.61)
  Top 0.254: IC5.1 48.1,19.53 48.9,20.32 51.56,20.32 v52.32,21.08
  Bottom 0.406: IOL.4 55.88,49.78 53.59,47.5 53.59,22.61 52.32,21.34 v52.32,21.08
IO4  (via drill 0.61)
  Top 0.254: IC5.2 47.6,20.3 48.26,20.95 49.53,20.95 v50.16,21.59
  Bottom 0.406: IOL.5 53.21,50.29 49.78,46.86 49.78,34.67 49.02,33.91 49.02,24.26 50.16,23.11 v50.16,21.59
IO5  (via drill 0.61)
  Top 0.254: IC5.9 43.34,18.26 v41.27,20.32
  Bottom 0.406: 39.69,26.35 39.37,26.04 | 39.69,26.35 48.64,35.18 48.64,48.13 50.8,50.29 IOL.6 | 39.69,26.35 39.23,25.9 39.23,22.36 v41.27,20.32
IO6  (via drill 0.61)
  Top 0.254: IC5.10 41.3,17.76 v40.01,19.05
  Bottom 0.406: IOL.7 48.26,49.53 47.5,48.77 47.37,35.43 38.34,26.41 38.47,20.58 v40.01,19.05
IO7  (via drill 0.61)
  Top 0.254: IC5.11 39.89,17.26 v38.1,19.05
  Bottom 0.406: IOL.8 45.72,49.02 46.1,48.64 46.1,35.43 37.58,26.91 37.58,19.57 v38.1,19.05
IO8  (via drill 0.61)
  Top 0.254: IC5.12 37.85,16.76 v37.47,17.14
  Bottom 0.406: IOH.1 41.66,49.28 40.64,48.26 40.64,31.37 36.83,27.56 36.83,17.78 v37.47,17.14
IO9  (via drill 0.61)
  Top 0.254: IC5.13 38.48,16.26 38.1,15.88 36.2,15.88 v34.92,17.14
  Bottom 0.406: IOH.2 39.12,31.11 35.56,27.56 35.56,17.78 v34.92,17.14
M8RXD
  Top 0.254: U3.9 23.5,33.17
  Top 0.305: RN4.7 56.62,33.89 54.99,32.26 31.62,32.26 30.73,33.15 24.26,33.15 24.23,33.17 23.5,33.17
M8TXD
  Top 0.254: U3.8 20.84,32.62 20.95,32.51 22.75,32.5 22.86,32.51
  Top 0.305: RN4.8 57.35,33.09 55.88,31.62 31.37,31.62 30.48,32.51 22.86,32.51
MISO  (via drill 0.61)
  Top 0.254: IC5.16 39.91,14.76 39.12,13.97 35.56,13.97 v35.12,13.53
  Bottom 0.406: IOH.5 31.5,46.23 35.05,42.67 35.05,31.24 32.38,28.57 32.38,21.34 29.84,18.8 29.84,17.53 33.85,13.53 v35.12,13.53 36.07,12.57 41.15,12.57 44.2,15.62 63.37,15.62 64.26,16.51 64.26,21.34 61.34,24.26 61.34,28.32 63.45,30.43 ICSP.1
MISO2  (via drill 0.61)
  Top 0.254: U3.17 20.8,38.07 22.48,39.75
  Top 0.305: 22.48,39.75 v22.48,41.53
  Bottom 0.305: v22.48,41.53 22.48,42.93 21.72,43.69 20.19,43.69 19.56,44.32 19.56,45.85 20.7,46.99 20.83,47.12 ICSP1.1
MOSI  (via drill 0.61)
  Top 0.254: v31.75,17.78 31.75,15.88 33.02,14.61 | IC5.15 39.39,15.26 38.73,14.61 33.27,14.61 33.27,13.72 36.32,10.67 v37.97,10.67
  Top 0.61: 33.27,14.61 33.02,14.61
  Bottom 0.381: 64.92,23.09 64.92,26.57
  Bottom 0.406: IOH.4 34.04,45.85 36.32,43.56 36.32,30.99 33.66,28.32 33.66,19.68 v31.75,17.78 | ICSP.4 66.18,27.83 64.92,26.57 | 64.92,23.09 65.79,22.23 65.79,15.75 63.88,13.84 47.88,13.84 46.99,12.95 44.96,12.95 42.67,10.67 v37.97,10.67
MOSI2  (via drill 0.61)
  Top 0.254: U3.16 22.07,36.67 22.86,37.47 v22.86,38.61
  Bottom 0.254: v22.86,38.61 22.86,39.62 21.34,41.15 20.07,41.15 19.56,41.66 19.56,43.05 18.29,44.32 ICSP1.4
N$1
  Top 0.305: RN2.1 27.27,41.53 L.A
N$2
  Top 0.254: U3.18 20.3,39.35 JP2.1
N$3
  Top 0.305: RN4.6 56.62,34.69 56.39,34.92 56.39,35.56 | 56.39,35.56 56.39,35.94 ON.A | RN4.5 56.95,35.49 56.9,35.43 56.52,35.43 56.39,35.56
N$4
  Top 0.254: U3.19 19.8,39 19.56,39.24 19.56,41.15 JP2.3
N$5
  Top 0.254: U3.20 19.3,38.61 18.29,39.62 JP2.2
N$6
  Top 0.254: JP2.4 17.02,41.15 17.02,39.24 17.78,38.48 18.54,38.48 18.8,38.22 U3.21
N$27
  pour Top: 0.64,52.58 11.81,52.58 11.81,47.62 0.64,47.62
N$35
  Top 0.305: RX.A 29.97,34.29 32.38,36.7 32.38,38.86 31.48,39.77 RN2.7
N$36
  Top 0.305: TX.A 29.25,36.57 30.86,36.57 31.75,37.47 31.75,38.61 31.39,38.97 RN2.6 28.98,38.97
PWRIN
  Top 0.61: 14.68,11.63 D1.A
  Top 0.813: 14.68,11.63 13.21,10.16 X1.2
RD+
  Top 0.254: U3.29 15.39,34.67 14.35,35.71 14.35,37.85 14.22,37.97 13.56,37.97 RN3.4
RD-
  Top 0.254: U3.30 14.99,34.17 13.53,35.63 RN3.1
RESET  (via drill 0.61)
  Top 0.254: IC5.29 58.03,16.76 v59.05,17.78
  Top 0.305: RESET-EN.1 27.18,29.21 27.43,29.46 27.81,29.46 C5.2 | 29.84,27.94 29.86,27.92
  Top 0.406: RESET-EN.2 RESET-EN.1 | ICSP.5 63.64,22.36 v59.05,17.78 | 29.21,27.94 RESET-EN.2 | 29.21,27.94 29.84,27.94 31.11,27.94 34.04,30.86 52.2,30.86 53.76,29.3 53.76,28.79 v57.15,25.4 | v57.15,25.4 58.85,25.4 RESET.1 | POWER.1 32.38,3.17 32.38,7.62 28.57,11.43 28.57,21.34 30.48,23.24 30.48,26.67 29.21,27.94 | v57.15,25.4 51.05,25.4 RESET.2 | RN1.4 28.61,27.85 RESET-EN.2
  Bottom 0.406: v59.05,17.78 59.05,23.5 v57.15,25.4
RESET2  (via drill 0.61)
  Top 0.254: U3.24 17.3,37.95 16.38,38.99 16.38,43.05 17.02,43.69 17.02,43.94
  Top 0.305: v22.48,46.35 22.48,47.75 21.46,48.77 17.02,48.77 ICSP1.5 17.02,46.23 17.02,43.94
  Top 0.406: RN1.6 v25.84,24.53 v25.83,24.54
  Bottom 0.406: v22.48,46.35 22.86,45.97 22.86,45.09 25.4,42.55 25.4,38.1 23.62,36.32 22.73,36.32 22.1,35.69 22.1,28.65 22.23,28.65 25.83,25.04 v25.83,24.54
RXLED
  Top 0.254: U3.10 26.14,33.67 RX.C
SCK  (via drill 0.61)
  Top 0.254: IC5.17 44.6,13.49 43.81,12.7 v43.18,12.7
  Top 0.406: RN2.8 29.77,40.57 31.11,41.91 31.11,44.83 v30.73,45.09
  Bottom 0.406: ICSP.3 63.58,27.89 62.1,26.42 62.1,24.77 65.02,21.84 65.02,16.13 63.63,14.73 45.21,14.73 v43.18,12.7 42.29,11.81 34.29,11.81 29.08,17.02 29.08,19.3 31.11,21.34 31.11,28.57 34.16,31.62 34.16,41.66 v30.73,45.09 28.96,46.86 IOH.6
SCK2
  Top 0.254: ICSP1.3 19.56,46.23 19.56,43.94 19.81,43.69 22.99,43.69 24.13,42.55 24.13,37.72 22.59,36.17 U3.15
SS  (via drill 0.61)
  Top 0.254: IC5.14 38.87,15.76 38.35,15.24 34.29,15.24 v33.02,16.51
  Bottom 0.406: IOH.3 36.58,45.47 37.59,44.45 37.59,30.86 34.54,27.81 34.54,18.67 33.02,17.14 v33.02,16.51
TXLED
  Top 0.254: U3.11 24.9,34.17 25.92,35.19 25.92,35.86
  Top 0.305: 25.92,35.86 TX.C
UGND
  Top 0.305: U3.28 15.83,35.17 14.99,36.02 14.99,39.88 14.22,40.64
  Top 0.406: C8.2 11.81,40.96 12.13,40.64 14.22,40.64
  Top 0.61: L1.1 9.53,45.09 11.81,42.8 C8.2
  Top 0.813: L1.1 8.85,44.41 4.45,40.01 4.45,37.47 5.08,36.83 6.5,36.83 X2.4
  Bottom 0.813: X2.4 5.06,36.85 4.45,37.47 4.45,40.01 5.71,41.27 10.03,41.27 GROUND.2
USBVCC
  Top 0.254: U3.31 15.64,33.67 14.99,33.02
  Top 0.406: 10.79,32.38 14.35,32.38 14.99,33.02
  Top 0.61: T1.1 3.43,24.47 F1.1 6.35,27.35 6.35,31.11 7.62,32.38 10.79,32.38
USHIELD  (via drill 0.61)
  Top 0.61: 8.78,33.54 9.41,33.54 9.53,33.66 Z2.2 | Z1.2 11.7,39.73 10.16,41.27 10.16,42.16 v9.53,42.8
  Top 0.813: L1.2 4.79,45.09 X2.P$1 | 8.78,33.54 5.25,33.54 X2.P$2
  Bottom 0.61: v9.53,42.8 5.11,42.8 X2.P$1
  Bottom 0.813: X2.P$2 3.68,34.67 2.67,35.69 2.67,41.78 3.81,42.93 X2.P$1
VIN  (via drill 0.61)
  Top 0.305: 12.7,19.68 12.7,20.18 16.65,24.13 24.77,24.13 25.4,23.5 26.29,23.5 26.52,23.73 RN1.7
  Top 0.61: PC1.+ 27.25,8.33 25.91,8.33 v25.65,8.08 25.4,8.33 22.78,8.33 22.23,8.89 22.23,9.27 20.83,10.79 20.61,10.79 D1.C 19.05,12.7 18.41,13.34 18.41,13.72 17.4,14.73 17.4,14.99 13.97,18.41 12.7,19.68 | v48.26,8.26 47.62,8.26 45.72,6.35 POWER.6 | IC1.3 11.75,19.71 IC2.3 12.7,19.68 | 12.7,19.68 12.84,19.68 12.7,19.68
  Bottom 0.61: v25.65,8.08 48.08,8.08 v48.26,8.26
VUCAP
  Top 0.254: U3.27 16.22,35.67 15.62,36.27
  Top 0.305: 15.62,36.27 15.62,40.51 14.22,41.91
  Top 0.61: 14.22,41.91 C8.1
XT1
  Top 0.254: U3.1 17.3,31.91 16.51,31.11 16.51,30.73 R1.1
  Top 0.61: Q1.2 13.97,29.59 C9.1 R1.1
XT2
  Top 0.254: 17.8,31.09 U3.2
  Top 0.305: R1.2 17.42,30.5 17.42,30.71 17.8,31.09
  Top 0.406: R1.2 C11.1 19.05,29.59 Q1.1
XTAL1
  Top 0.254: IC5.7 45.1,20.66 Y2.3
  Top 0.406: Y2.3 41.64,26.65 R2.1
XTAL2
  Top 0.254: IC5.8 44.6,20.16 42.55,22.23 40.01,22.23 39.64,22.59 Y2.1
  Top 0.406: Y2.1 39.66,24.15 39.66,26.54 R2.2
XUSB
  Top 0.813: F1.2 2.5,27.98 1.4,29.08 1.4,33.78 2.54,34.92 7.62,34.92 8.51,35.81 X2.1

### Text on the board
Top: Reference Designs ARE PROVIDED "AS IS" AND "WITH ALL FAULTS. Arduino DISCLAIMS ALL OTHER WARRANTIES, EXPRESS OR IMPLIED, | REGARDING PRODUCTS, INCLUDING BUT NOT LIMITED TO, ANY IMPLIED WARRANTIES OF MERCHANTABILITY OR FITNESS FOR A PARTICULAR PURPOSE | Arduino may make changes to specifications and product descriptions at any time, without notice. The Customer must not | rely on the absence or characteristics of any features or instructions marked "reserved" or "undefined." Arduino reserves | these for future definition and shall have no responsibility whatsoever for conflicts or incompatibilities arising from future changes to them. | The product information on the Web Site or Materials is subject to change without notice. Do not finalize a design with this information.
Bottom: 2010-G
tPlace: MADE IN | 13 | 12 | 11 | 10 | 9 | 8 | 7 | 6 | 5 | 4 | 3 | 2 | 1 | 0 | ITALY | SMD | Edition
tNames: M.Banzi | D.Cuartielles | T.Igoe | AREF | GND | G.Martino | # | # | # | # | D.Mellis | # | # | DIGITAL | [#=PWM] | TX | RX | TM | TX | Arduino | RX | UNO | www.arduino.cc | 1 | ANALOG IN | RESET | 3V3 | 5V | GND | VIN | A0 | A1 | A2 | A3 | A4 | A5
bNames: MADE IN | designed by | MADE IN | ITALY | tinker it | ITALY | designed by | tinker it | ATMEGA328
ReferenceLC: L | TX | RX | PC1 | PC2
214bmp: D:/SmartProjects/Snc/a4_bn_logo2.bmp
